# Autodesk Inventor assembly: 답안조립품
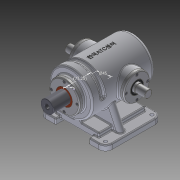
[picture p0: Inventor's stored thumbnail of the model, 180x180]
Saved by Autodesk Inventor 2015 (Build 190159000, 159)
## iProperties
Created: 2015-10
Part Number: 답안조립품
Document SubType Name: Assembly
Designer: youjin21
Author: youjin21
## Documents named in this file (13)
- C:\Users\youjin21\Desktop\351019V1008\답안조립품.iam
- C:\Users\youjin21\Desktop\351019V1008\본체.ipt
- C:\Users\youjin21\Desktop\351019V1008\슬라이드 커버.ipt
- C:\Users\youjin21\Desktop\351019V1008\M4x0.7.ipt
- C:\Users\youjin21\Desktop\351019V1008\축 커버.ipt
- C:\Users\youjin21\Desktop\351019V1008\부시.ipt
- C:\Users\youjin21\Desktop\351019V1008\베어링 6205.ipt
- 베어링 6205.ipt
- C:\Users\youjin21\Desktop\351019V1008\오일실.ipt
- 오일실.ipt
- C:\Users\youjin21\Desktop\351019V1008\편심축.ipt
- C:\Users\youjin21\Desktop\351019V1008\가변스프링.ipt
- C:\Users\youjin21\Desktop\351019V1008\슬라이드.ipt
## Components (13 placed, 2 different names)
1. 가변스프링:1 — Mate:22, Mate:23, Mate:24, Mate:25
2. M4x0.7:1 — Insert:1
3. M4x0.7:2
4. M4x0.7:3
5. M4x0.7:4
6. M4x0.7:6 — Insert:3
7. M4x0.7:7
8. M4x0.7:8
9. M4x0.7:9
10. M4x0.7:5 — Insert:2
11. M4x0.7:10
12. M4x0.7:11
13. M4x0.7:12
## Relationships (7: Mate 4, Insert 3)
- Insert:1: M4x0.7:1
- Insert:2: M4x0.7:5
- Insert:3: M4x0.7:6
- Mate:22: 가변스프링:1
- Mate:23: 가변스프링:1
- Mate:24: 가변스프링:1
- Mate:25: 가변스프링:1
